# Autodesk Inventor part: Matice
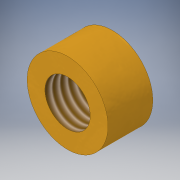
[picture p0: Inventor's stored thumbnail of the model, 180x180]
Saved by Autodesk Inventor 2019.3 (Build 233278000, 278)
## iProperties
Created: 2019-01
Part Number: Matice
Material: Ocel, měkká
Document SubType Name: Modeling
Designer: B-hon
Density: 7.85 g/cm^3
Appearance: Svar – mosaz
Author: B-hon
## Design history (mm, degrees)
sketch "Náčrt1"
  geometry: C1 r 9 at (0, 0); 1 further point
  constraints: 1 centre point, 1 coincident
  dimensions: "d0" = 18 diameter of C1
extrude "Vysunutí1" new body sketch "Náčrt1" distance "d1" = 10; taper "d2" = 0 deg
sketch "Náčrt2"
  geometry: C1 r 9 at (0, 0) reference; 2 further points
  constraints: 1 coincident
hole "Díra1" sketch "Náčrt2" at (0, 0) diameter "d3" = 10.106; stored, may be unused: countersink angle "d7" = 90 deg, drill point angle "d9" = 118 deg; dims "d4" = 24, "d5" = 4, "d6" = 2, "d8" = 32.3
node "Těleso1"
